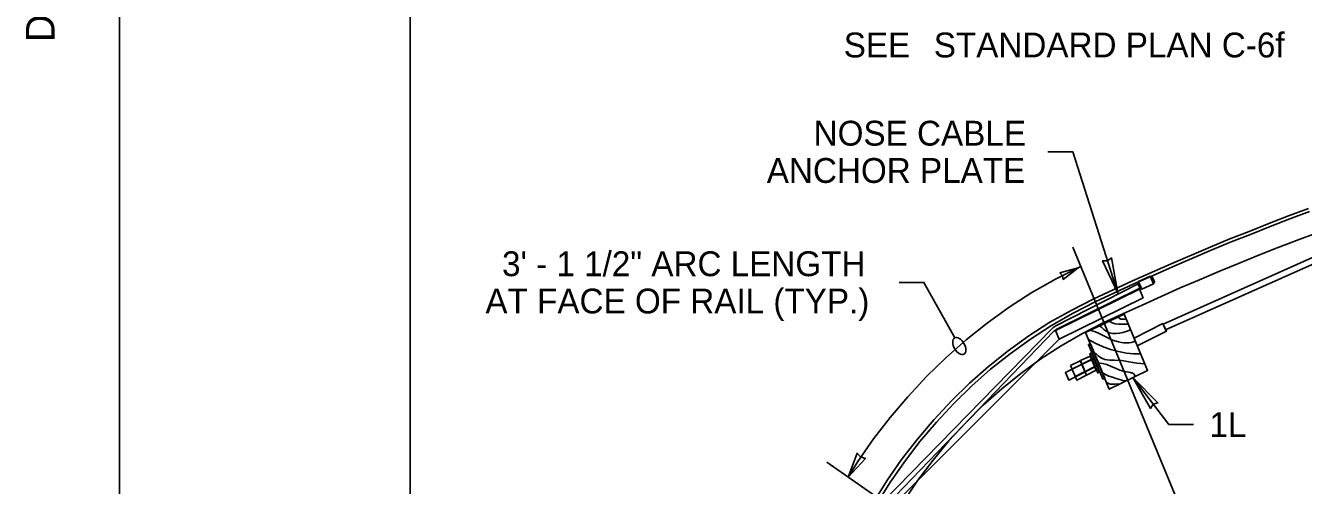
# Model space of a CAD drawing. Extents: x 1312564.2 to 1312581.5, y 1207298.4 to 1207352.6.
# Drawn here: x 1312564.175 to 1312568.294, y 1207332.627 to 1207334.109 of the extents above; entities that cross this region are included whole.
import ezdxf

# ---------------------------------------------------------------- set-up
doc = ezdxf.new("R2010")
doc.units = 0
for name, color, linetype in [('Level 1', 7, 'Continuous'), ('Level 15', 7, 'Continuous'), ('Level 16', 7, 'Continuous'), ('Level 2', 7, 'Continuous'), ('Level 20', 7, 'Continuous'), ('Level 3', 7, 'Continuous'), ('Level 6', 7, 'Continuous'), ('Level 62', 7, 'Continuous')]:
    doc.layers.add(name, color=color, linetype=linetype)

msp = doc.modelspace()

# ---------------------------------------------------------------- linework, layer by layer
at = {"layer": 'Level 1'}
msp.add_line((1312565.4155, 1207337.9084), (1312565.4155, 1207327.5334), dxfattribs=at)
at = {"layer": 'Level 15'}
for p, q in [((1312567.761, 1207333.2763), (1312567.4958, 1207333.141)), ((1312567.94, 1207332.823), (1312567.8599, 1207332.823))]:
    msp.add_line(p, q, dxfattribs=at)
for points in [[(1312567.4705, 1207333.7019), (1312567.5506, 1207333.7019), (1312567.6956, 1207333.2467)], [(1312568.3354, 1207333.4401), (1312568.2719, 1207333.4167), (1312568.2094, 1207333.3922), (1312568.1469, 1207333.3677), (1312568.0844, 1207333.3422), (1312568.0219, 1207333.3166), (1312567.9594, 1207333.29), (1312567.8969, 1207333.2634), (1312567.8354, 1207333.2357), (1312567.7739, 1207333.208), (1312567.7124, 1207333.1804), (1312567.6509, 1207333.1516)], [(1312568.4691, 1207333.4048), (1312567.8493, 1207333.1282), (1312567.8424, 1207333.1463), (1312568.4634, 1207333.4234)], [(1312568.2739, 1207331.6432), (1312567.5508, 1207333.3943)], [(1312567.5763, 1207333.3326), (1312567.4947, 1207333.2912), (1312567.4188, 1207333.2488), (1312567.3458, 1207333.2015), (1312567.2749, 1207333.1504), (1312567.2065, 1207333.0965), (1312567.1416, 1207333.0383), (1312567.0793, 1207332.9783), (1312567.0185, 1207332.913), (1312566.9626, 1207332.8463), (1312566.9089, 1207332.7773), (1312566.8575, 1207332.7038), (1312566.8272, 1207332.6543)], [(1312566.991, 1207333.2813), (1312567.071, 1207333.2813), (1312567.1703, 1207333.1024)], [(1312567.767, 1207333.2627), (1312567.5032, 1207333.1331)], [(1312567.6509, 1207333.1516), (1312567.5815, 1207333.1165), (1312567.513, 1207333.0771), (1312567.4476, 1207333.0345), (1312567.3831, 1207332.9877), (1312567.3216, 1207332.9387), (1312567.262, 1207332.8855), (1312567.2055, 1207332.8291), (1312567.1509, 1207332.7705), (1312567.1003, 1207332.7088), (1312567.0517, 1207332.6439), (1312567.0061, 1207332.5768)], [(1312567.7489, 1207333.1021), (1312567.8414, 1207333.1484), (1312567.8523, 1207333.1239), (1312567.7599, 1207333.0777)], [(1312567.6357, 1207333.0154), (1312567.5378, 1207332.9664), (1312567.5269, 1207332.9909), (1312567.6251, 1207333.0401)], [(1312567.5477, 1207333.0015), (1312567.5785, 1207333.0164)], [(1312567.5805, 1207333.0175), (1312567.6112, 1207333.0313)], [(1312567.5904, 1207332.9941), (1312567.6212, 1207333.01)], [(1312567.5587, 1207332.9781), (1312567.5894, 1207332.9941)], [(1312567.8599, 1207332.823), (1312567.744, 1207332.9753)], [(1312568.2739, 1207331.6432), (1312566.7582, 1207332.7019)]]:
    msp.add_lwpolyline(points, dxfattribs=at)
for points in [[(1312567.5682, 1207333.3285), (1312567.5094, 1207333.3118), (1312567.5172, 1207333.3026), (1312567.52, 1207333.2909)], [(1312567.7779, 1207333.2319), (1312567.766, 1207333.2596), (1312567.4951, 1207333.1265), (1312567.507, 1207333.0988)], [(1312567.6073, 1207333.0835), (1312567.6539, 1207332.9728), (1312567.6479, 1207332.9696), (1312567.6013, 1207333.0814)], [(1312567.6112, 1207333.0548), (1312567.637, 1207332.993), (1312567.6311, 1207332.9898), (1312567.6053, 1207333.0516)], [(1312567.5438, 1207333.0132), (1312567.5745, 1207333.0281), (1312567.5944, 1207332.9824), (1312567.5636, 1207332.9664)], [(1312567.5755, 1207333.0292), (1312567.6063, 1207333.0441), (1312567.6261, 1207332.9983), (1312567.5954, 1207332.9824)], [(1312567.744, 1207332.9753), (1312567.8013, 1207332.8753), (1312567.81, 1207332.8886), (1312567.8251, 1207332.8934)], [(1312566.8272, 1207332.6543), (1312566.8824, 1207332.7144), (1312566.867, 1207332.7194), (1312566.8556, 1207332.7307)]]:
    msp.add_lwpolyline(points, close=True, dxfattribs=at)
msp.add_ellipse((1312567.1849, 1207333.0762), major_axis=(-0.015, 0.026), ratio=0.57735, dxfattribs=at)
at = {"layer": 'Level 16'}
for points in [[(1312568.3099, 1207333.5192), (1312568.2463, 1207333.4958), (1312568.1827, 1207333.4713), (1312568.1192, 1207333.4457), (1312568.0566, 1207333.4212), (1312567.993, 1207333.3945), (1312567.8679, 1207333.3412), (1312567.7427, 1207333.2858), (1312567.6812, 1207333.257), (1312567.6187, 1207333.2283)], [(1312568.3136, 1207333.5093), (1312568.2501, 1207333.4859), (1312568.1866, 1207333.4614), (1312568.1231, 1207333.4358), (1312568.0606, 1207333.4114), (1312567.9971, 1207333.3847), (1312567.9346, 1207333.3581), (1312567.8721, 1207333.3315), (1312567.8096, 1207333.3038), (1312567.7471, 1207333.2762), (1312567.6856, 1207333.2474), (1312567.6231, 1207333.2187)], [(1312567.6189, 1207333.2285), (1312567.5474, 1207333.1922), (1312567.4767, 1207333.1527), (1312567.409, 1207333.1089), (1312567.3424, 1207333.0609), (1312567.2787, 1207333.0107), (1312567.218, 1207332.9562), (1312567.1593, 1207332.8997), (1312567.1025, 1207332.8388), (1312567.0498, 1207332.7758), (1312566.9991, 1207332.7107), (1312566.9513, 1207332.6423), (1312566.9076, 1207332.5708)], [(1312567.6231, 1207333.2187), (1312567.5517, 1207333.1825), (1312567.4823, 1207333.142), (1312567.4148, 1207333.0984), (1312567.3493, 1207333.0516), (1312567.2859, 1207333.0015), (1312567.2253, 1207332.9483), (1312567.1668, 1207332.8908), (1312567.1113, 1207332.8312), (1312567.0577, 1207332.7684), (1312567.0081, 1207332.7035), (1312566.9615, 1207332.6353), (1312566.9168, 1207332.5651)]]:
    msp.add_lwpolyline(points, dxfattribs=at)
at = {"layer": 'Level 2'}
msp.add_lwpolyline([(1312564.478, 1207327.2209), (1312581.478, 1207327.2209), (1312581.478, 1207338.2209), (1312564.478, 1207338.2209)], close=True, dxfattribs=at)
at = {"layer": 'Level 3'}
for p, q in [((1312567.4832, 1207333.1319), (1312566.9393, 1207332.5753)), ((1312566.9525, 1207332.5662), (1312567.49, 1207333.1237)), ((1312566.9655, 1207332.5569), (1312567.507, 1207333.0988))]:
    msp.add_line(p, q, dxfattribs=at)
msp.add_lwpolyline([(1312567.5914, 1207333.1197), (1312567.7164, 1207333.1793), (1312567.7918, 1207332.9973), (1312567.6678, 1207332.9377)], close=True, dxfattribs=at)
for points in [[(1312567.638, 1207333.1399), (1312567.641, 1207333.1378), (1312567.644, 1207333.1357), (1312567.6469, 1207333.1335), (1312567.6489, 1207333.1314), (1312567.6509, 1207333.1293), (1312567.6539, 1207333.1271), (1312567.6559, 1207333.125), (1312567.6678, 1207333.1186), (1312567.6787, 1207333.1165), (1312567.6896, 1207333.1165), (1312567.7015, 1207333.1176), (1312567.7124, 1207333.1197), (1312567.7223, 1207333.1229), (1312567.7313, 1207333.1261), (1312567.7372, 1207333.1293)], [(1312567.6688, 1207333.1569), (1312567.6777, 1207333.1506), (1312567.6876, 1207333.1474), (1312567.6975, 1207333.1463), (1312567.7094, 1207333.1463), (1312567.7204, 1207333.1463), (1312567.7303, 1207333.1463)], [(1312567.6965, 1207333.1708), (1312567.7005, 1207333.1655), (1312567.7055, 1207333.1633), (1312567.7104, 1207333.1633), (1312567.7174, 1207333.1633), (1312567.7233, 1207333.1633)], [(1312567.6013, 1207333.0973), (1312567.6231, 1207333.0856), (1312567.6469, 1207333.075), (1312567.6717, 1207333.0654), (1312567.6975, 1207333.059), (1312567.7233, 1207333.0537), (1312567.7471, 1207333.0516), (1312567.769, 1207333.0516)], [(1312567.6102, 1207333.1261), (1312567.6241, 1207333.1218), (1312567.636, 1207333.1165), (1312567.6469, 1207333.1112), (1312567.6569, 1207333.1058), (1312567.6678, 1207333.1005), (1312567.6787, 1207333.0952), (1312567.6985, 1207333.0899), (1312567.7075, 1207333.0877), (1312567.7154, 1207333.0867), (1312567.7243, 1207333.0867), (1312567.7323, 1207333.0867), (1312567.7392, 1207333.0877), (1312567.7461, 1207333.0899), (1312567.7521, 1207333.0931)], [(1312567.6192, 1207333.0548), (1312567.6212, 1207333.0548), (1312567.6231, 1207333.0537), (1312567.6251, 1207333.0516), (1312567.6271, 1207333.0505), (1312567.6291, 1207333.0484), (1312567.6301, 1207333.0473), (1312567.6321, 1207333.0452), (1312567.64, 1207333.0388), (1312567.6469, 1207333.0356), (1312567.6539, 1207333.0324), (1312567.6618, 1207333.0313), (1312567.6698, 1207333.0303), (1312567.6777, 1207333.0303), (1312567.6856, 1207333.0303), (1312567.7075, 1207333.0292), (1312567.7204, 1207333.0271), (1312567.7323, 1207333.0249), (1312567.7442, 1207333.0228), (1312567.7571, 1207333.0207), (1312567.77, 1207333.0196), (1312567.7829, 1207333.0186)], [(1312567.6321, 1207333.0218), (1312567.6469, 1207333.0196), (1312567.6608, 1207333.0164), (1312567.6747, 1207333.01), (1312567.6886, 1207333.0047), (1312567.7025, 1207332.9983), (1312567.7174, 1207332.9941), (1312567.7362, 1207332.9909), (1312567.7392, 1207332.9898), (1312567.7422, 1207332.9898), (1312567.7452, 1207332.9877), (1312567.7481, 1207332.9856), (1312567.7501, 1207332.9824), (1312567.7531, 1207332.9781)], [(1312567.646, 1207332.9898), (1312567.6559, 1207332.9845), (1312567.6668, 1207332.9792), (1312567.6787, 1207332.976), (1312567.6906, 1207332.9717), (1312567.7055, 1207332.9675), (1312567.7085, 1207332.9664), (1312567.7114, 1207332.9653), (1312567.7144, 1207332.9643), (1312567.7184, 1207332.9643), (1312567.7213, 1207332.9643)], [(1312567.6598, 1207332.96), (1312567.6658, 1207332.9558), (1312567.6717, 1207332.9536), (1312567.6797, 1207332.9536), (1312567.6866, 1207332.9536), (1312567.6946, 1207332.9547), (1312567.7005, 1207332.9536)]]:
    msp.add_lwpolyline(points, dxfattribs=at)
at = {"layer": 'Level 6'}
for p, q in [((1312567.8113, 1207333.2769), (1312567.8005, 1207333.301)), ((1312567.7732, 1207333.2598), (1312567.7624, 1207333.2839))]:
    msp.add_line(p, q, dxfattribs=at)
for points in [[(1312567.6956, 1207333.2467), (1312567.6467, 1207333.3511), (1312567.6625, 1207333.3506), (1312567.6752, 1207333.3601)], [(1312567.7602, 1207333.2781), (1312567.7674, 1207333.262), (1312567.7732, 1207333.2598), (1312567.8113, 1207333.2769), (1312567.8135, 1207333.2827), (1312567.8063, 1207333.2988), (1312567.8005, 1207333.301), (1312567.7624, 1207333.2839)]]:
    msp.add_lwpolyline(points, close=True, dxfattribs=at)
for centre, start in [((1312567.5185, 1207333.0964), 117.0277), ((1312567.5252, 1207333.0882), 116.1661)]:
    msp.add_arc(centre, 0.05, start, 134.8055, dxfattribs=at)

# ---------------------------------------------------------------- texts
at = {"layer": 'Level 20'}
for s, height, p in [('SEE ', 0.08008, (1312566.8125, 1207334.006)), ('STANDARD PLAN C-6f', 0.080077, (1312567.1027, 1207334.006)), ('NOSE CABLE', 0.08008, (1312566.7154, 1207333.7219)), ('ANCHOR PLATE', 0.080077, (1312566.5644, 1207333.6018)), ('3\' - 1 1/2" ARC LENGTH ', 0.080077, (1312565.7112, 1207333.3013)), ('AT FACE OF RAIL (TYP.)', 0.080077, (1312565.6575, 1207333.1812)), ('1L', 0.08008, (1312567.9909, 1207332.783))]:
    msp.add_text(s, height=height, dxfattribs=at).set_placement(p)
at = {"layer": 'Level 62'}
msp.add_text('DRAWN BY:  BILL BERENS', height=0.09216, rotation=90, dxfattribs=at).set_placement((1312564.2689, 1207334.0556))

doc.saveas('drawing.dxf')
